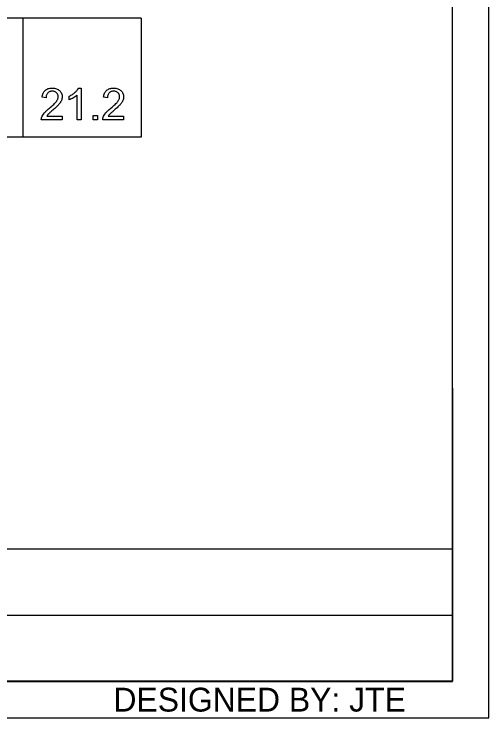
# Model space of a CAD drawing. Extents: x 187716 to 188418, y 178603 to 179533.
# Drawn here: x 188274.8 to 188418.1, y 178602.7 to 178815.1 of the extents above; entities that cross this region are included whole.
import ezdxf

# ---------------------------------------------------------------- set-up
doc = ezdxf.new("R2010")
doc.units = 0
doc.layers.add('Default', color=7, linetype='Continuous')

msp = doc.modelspace()

# ---------------------------------------------------------------- linework, layer by layer
at = {"layer": 'Default'}
for p, q in [((188313.17, 178813.81), (187813.36, 178813.81)), ((188277.45, 178813.81), (188277.45, 178777.91)), ((188313.17, 178813.81), (188313.17, 178777.91)), ((188313.17, 178777.91), (187813.36, 178777.91)), ((188407.12, 178702.24), (188407.12, 178613.74)), ((188168.76, 178653.73), (188407.12, 178653.73)), ((188168.76, 178633.73), (188407.12, 178633.73)), ((188407.12, 178613.74), (188108.85, 178613.74))]:
    msp.add_line(p, q, dxfattribs=at)
for points in [[(188418.09, 178602.69), (188418.09, 179533.02), (187715.97, 179533.02), (187715.97, 178602.69)], [(188407.12, 178613.73), (188407.12, 179522.02), (187727.02, 179522.02), (187727.02, 178613.73)]]:
    msp.add_lwpolyline(points, close=True, dxfattribs=at)
for points in [[(188289.28, 178783.14), (188283, 178783.14), (188283, 178783.26), (188283.01, 178783.37), (188283.01, 178783.47), (188283.03, 178783.56), (188283.04, 178783.65), (188283.07, 178783.75), (188283.1, 178783.85), (188283.14, 178783.96), (188283.27, 178784.29), (188283.45, 178784.61), (188283.66, 178784.93), (188283.91, 178785.25), (188284.05, 178785.41), (188284.21, 178785.58), (188284.38, 178785.75), (188284.56, 178785.93), (188284.76, 178786.11), (188284.97, 178786.3), (188285.2, 178786.5), (188285.44, 178786.69), (188285.81, 178787), (188286.15, 178787.3), (188286.46, 178787.58), (188286.74, 178787.84), (188286.98, 178788.08), (188287.2, 178788.31), (188287.39, 178788.52), (188287.54, 178788.72), (188287.67, 178788.91), (188287.78, 178789.09), (188287.88, 178789.27), (188287.95, 178789.46), (188288.01, 178789.63), (188288.06, 178789.81), (188288.08, 178789.98), (188288.09, 178790.15), (188288.08, 178790.32), (188288.06, 178790.49), (188288.02, 178790.64), (188287.97, 178790.8), (188287.9, 178790.94), (188287.81, 178791.08), (188287.71, 178791.21), (188287.6, 178791.33), (188287.47, 178791.45), (188287.33, 178791.54), (188287.18, 178791.63), (188287.02, 178791.69), (188286.86, 178791.75), (188286.68, 178791.79), (188286.49, 178791.81), (188286.3, 178791.82), (188286.1, 178791.81), (188285.9, 178791.78), (188285.72, 178791.74), (188285.54, 178791.68), (188285.38, 178791.61), (188285.23, 178791.52), (188285.08, 178791.41), (188284.95, 178791.29), (188284.83, 178791.15), (188284.72, 178791.01), (188284.63, 178790.84), (188284.56, 178790.67), (188284.51, 178790.48), (188284.46, 178790.29), (188284.44, 178790.08), (188284.43, 178789.86), (188283.24, 178789.98), (188283.28, 178790.31), (188283.34, 178790.62), (188283.42, 178790.91), (188283.53, 178791.18), (188283.66, 178791.43), (188283.8, 178791.66), (188283.97, 178791.87), (188284.16, 178792.06), (188284.37, 178792.23), (188284.6, 178792.37), (188284.84, 178792.49), (188285.1, 178792.59), (188285.39, 178792.67), (188285.68, 178792.72), (188285.99, 178792.76), (188286.33, 178792.77), (188286.66, 178792.76), (188286.97, 178792.72), (188287.26, 178792.66), (188287.54, 178792.58), (188287.8, 178792.47), (188288.04, 178792.34), (188288.27, 178792.18), (188288.48, 178792), (188288.67, 178791.8), (188288.83, 178791.6), (188288.97, 178791.38), (188289.08, 178791.14), (188289.17, 178790.9), (188289.24, 178790.65)], [(188293.82, 178783.14), (188293.82, 178790.63), (188293.6, 178790.43), (188293.33, 178790.23), (188293.04, 178790.03), (188292.71, 178789.83), (188292.36, 178789.63), (188292.04, 178789.47), (188291.74, 178789.33), (188291.45, 178789.21), (188291.45, 178790.35), (188291.7, 178790.47), (188291.94, 178790.6), (188292.17, 178790.73), (188292.39, 178790.87), (188292.6, 178791.01), (188292.81, 178791.16), (188293, 178791.32), (188293.19, 178791.48), (188293.37, 178791.64), (188293.54, 178791.81), (188293.69, 178791.97), (188293.83, 178792.13), (188293.95, 178792.29), (188294.07, 178792.45), (188294.16, 178792.61), (188294.25, 178792.77), (188295.01, 178792.77), (188295.01, 178783.14), (188293.82, 178783.14)], [(188307.83, 178783.14), (188301.54, 178783.14), (188301.54, 178783.26), (188301.54, 178783.37), (188301.55, 178783.47), (188301.57, 178783.56), (188301.58, 178783.65), (188301.61, 178783.75), (188301.64, 178783.85), (188301.68, 178783.96), (188301.81, 178784.29), (188301.99, 178784.61), (188302.2, 178784.93), (188302.45, 178785.25), (188302.59, 178785.41), (188302.75, 178785.58), (188302.92, 178785.75), (188303.1, 178785.93), (188303.3, 178786.11), (188303.51, 178786.3), (188303.74, 178786.5), (188303.98, 178786.69), (188304.35, 178787), (188304.69, 178787.3), (188305, 178787.58), (188305.28, 178787.84), (188305.52, 178788.08), (188305.74, 178788.31), (188305.93, 178788.52), (188306.08, 178788.72), (188306.21, 178788.91), (188306.32, 178789.09), (188306.42, 178789.27), (188306.49, 178789.46), (188306.55, 178789.63), (188306.6, 178789.81), (188306.62, 178789.98), (188306.63, 178790.15), (188306.63, 178790.32), (188306.6, 178790.49), (188306.56, 178790.64), (188306.51, 178790.8), (188306.44, 178790.94), (188306.35, 178791.08), (188306.25, 178791.21), (188306.13, 178791.33), (188306.01, 178791.45), (188305.87, 178791.54), (188305.72, 178791.63), (188305.56, 178791.69), (188305.4, 178791.75), (188305.22, 178791.79), (188305.03, 178791.81), (188304.84, 178791.82), (188304.63, 178791.81), (188304.44, 178791.78), (188304.26, 178791.74), (188304.08, 178791.68), (188303.92, 178791.61), (188303.77, 178791.52), (188303.62, 178791.41), (188303.49, 178791.29), (188303.37, 178791.15), (188303.26, 178791.01), (188303.17, 178790.84), (188303.1, 178790.67), (188303.04, 178790.48), (188303.01, 178790.29), (188302.98, 178790.08), (188302.97, 178789.86), (188301.78, 178789.98), (188301.82, 178790.31), (188301.88, 178790.62), (188301.96, 178790.91), (188302.07, 178791.18), (188302.19, 178791.43), (188302.34, 178791.66), (188302.51, 178791.87), (188302.7, 178792.06), (188302.91, 178792.23), (188303.14, 178792.37), (188303.39, 178792.49), (188303.65, 178792.59), (188303.93, 178792.67), (188304.22, 178792.72), (188304.53, 178792.76), (188304.87, 178792.77), (188305.19, 178792.76), (188305.51, 178792.72), (188305.8, 178792.66), (188306.08, 178792.58), (188306.34, 178792.47), (188306.58, 178792.34), (188306.81, 178792.18), (188307.02, 178792), (188307.21, 178791.8), (188307.37, 178791.6), (188307.51, 178791.38), (188307.63, 178791.14), (188307.71, 178790.9), (188307.78, 178790.65)], [(188289.24, 178790.65), (188289.27, 178790.38), (188289.28, 178790.1), (188289.27, 178789.82), (188289.23, 178789.54), (188289.16, 178789.26), (188289.05, 178788.98), (188288.99, 178788.84), (188288.92, 178788.7), (188288.83, 178788.56), (188288.75, 178788.41), (188288.64, 178788.26), (188288.53, 178788.11), (188288.41, 178787.96), (188288.27, 178787.8), (188288.13, 178787.64), (188287.96, 178787.46), (188287.77, 178787.27), (188287.55, 178787.06), (188287.31, 178786.84), (188287.06, 178786.61), (188286.77, 178786.36), (188286.48, 178786.1), (188286.22, 178785.89), (188285.99, 178785.7), (188285.79, 178785.52), (188285.6, 178785.36), (188285.45, 178785.22), (188285.32, 178785.09), (188285.21, 178784.99), (188285.13, 178784.9), (188284.98, 178784.74), (188284.86, 178784.58), (188284.74, 178784.42), (188284.63, 178784.26), (188289.28, 178784.26), (188289.28, 178783.14)], [(188307.78, 178790.65), (188307.81, 178790.38), (188307.83, 178790.1), (188307.81, 178789.82), (188307.77, 178789.54), (188307.69, 178789.26), (188307.6, 178788.98), (188307.53, 178788.84), (188307.46, 178788.7), (188307.38, 178788.56), (188307.28, 178788.41), (188307.18, 178788.26), (188307.07, 178788.11), (188306.95, 178787.96), (188306.82, 178787.8), (188306.67, 178787.64), (188306.5, 178787.46), (188306.31, 178787.27), (188306.09, 178787.06), (188305.86, 178786.84), (188305.6, 178786.61), (188305.32, 178786.36), (188305.01, 178786.1), (188304.76, 178785.89), (188304.53, 178785.7), (188304.33, 178785.52), (188304.15, 178785.36), (188303.99, 178785.22), (188303.86, 178785.09), (188303.75, 178784.99), (188303.66, 178784.9), (188303.53, 178784.74), (188303.4, 178784.58), (188303.28, 178784.42), (188303.17, 178784.26), (188307.83, 178784.26), (188307.83, 178783.14)], [(188298.6, 178784.49), (188299.95, 178784.49), (188299.95, 178783.14), (188298.6, 178783.14), (188298.6, 178784.49)]]:
    msp.add_lwpolyline(points, dxfattribs=at)

# ---------------------------------------------------------------- texts
msp.add_text('DESIGNED BY: JTE', height=7.198, dxfattribs=at).set_placement((188304.77, 178604.61))

doc.saveas('drawing.dxf')
